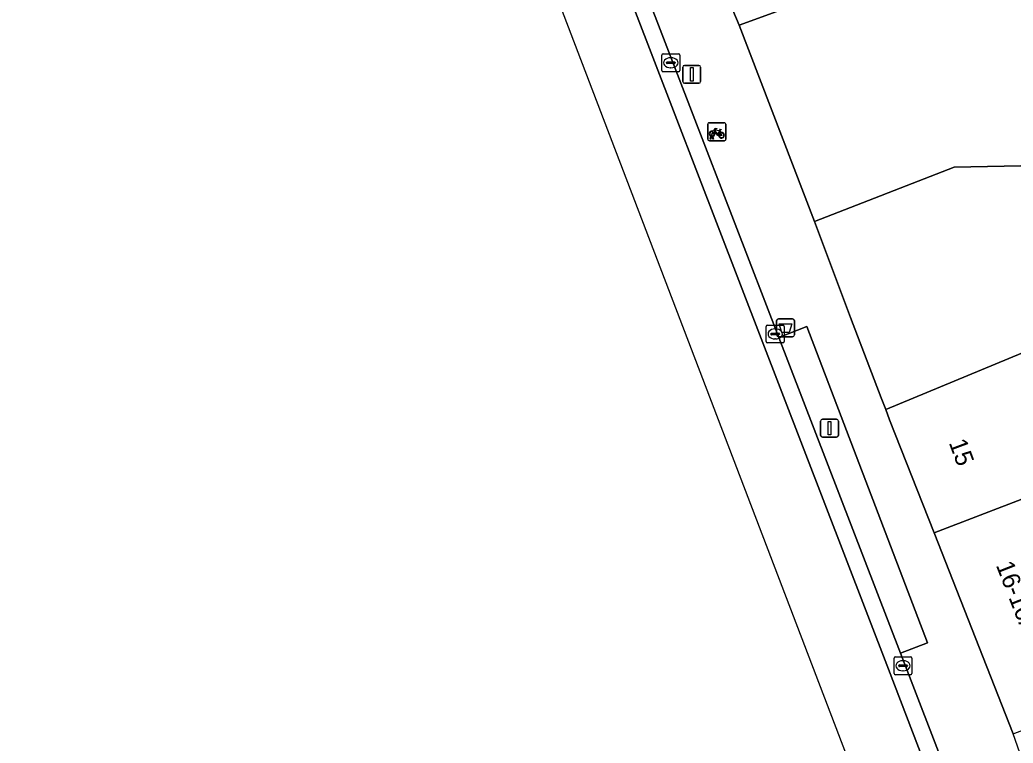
# Model space of a CAD drawing. Extents: x 160856 to 161310, y 384024 to 384878.
# Drawn here: x 160889.1 to 160944.6, y 384634.5 to 384674.8 of the extents above; entities that cross this region are included whole.
import ezdxf

# ---------------------------------------------------------------- set-up
doc = ezdxf.new("R2010")
doc.units = 0
for name, color, linetype in [('IMGEO_Afvalbak', 7, 'Continuous'), ('IMGEO_Fietsenrek', 7, 'Continuous'), ('IMGEO_Fietspad_gesloten', 7, 'Continuous'), ('IMGEO_Fietspad_open', 7, 'Continuous'), ('IMGEO_Kolk', 7, 'Continuous'), ('IMGEO_Lichtmast', 7, 'Continuous'), ('IMGEO_Pand', 7, 'Continuous'), ('IMGEO_Pand_nummerreeks', 7, 'Continuous'), ('IMGEO_Verkeerseiland_open', 7, 'Continuous'), ('IMGEO_Voetpad_open', 7, 'Continuous')]:
    doc.layers.add(name, color=color, linetype=linetype)

msp = doc.modelspace()

# ---------------------------------------------------------------- linework, layer by layer
at = {"layer": 'IMGEO_Afvalbak'}
for p, q in [((160931.361, 384657.241), (160931.361, 384658.041)), ((160931.361, 384658.041), (160931.361, 384657.241)), ((160931.461, 384658.141), (160932.251, 384658.141)), ((160932.251, 384658.141), (160931.461, 384658.141)), ((160932.351, 384658.041), (160932.351, 384657.241)), ((160932.351, 384657.241), (160932.351, 384658.041)), ((160932.251, 384657.141), (160931.461, 384657.141)), ((160931.461, 384657.141), (160932.251, 384657.141))]:
    msp.add_line(p, q, dxfattribs=at)
msp.add_lwpolyline([(160931.504, 384657.855), (160932.208, 384657.855), (160932.059, 384657.385), (160931.653, 384657.385), (160931.504, 384657.855)], dxfattribs=at)
for centre, start, end in [((160931.461, 384658.041), 90, 180), ((160931.461, 384658.041), 90, 180), ((160932.251, 384658.041), 0, 90), ((160932.251, 384658.041), 360, 90), ((160931.461, 384657.241), 180, 270), ((160931.461, 384657.241), 180, 270), ((160932.251, 384657.241), 270, 0), ((160932.251, 384657.241), 270, 0)]:
    msp.add_arc(centre, 0.1, start, end, dxfattribs=at)
at = {"layer": 'IMGEO_Fietsenrek'}
for p, q in [((160927.524, 384668.162), (160927.524, 384669.003)), ((160927.524, 384669.003), (160927.524, 384668.162)), ((160927.599, 384669.087), (160928.44, 384669.087)), ((160928.44, 384669.087), (160927.599, 384669.087)), ((160928.524, 384669.012), (160928.524, 384668.171)), ((160928.524, 384668.171), (160928.524, 384669.012)), ((160928.211, 384668.636), (160928.247, 384668.541)), ((160928.449, 384668.087), (160927.608, 384668.087)), ((160927.608, 384668.087), (160928.449, 384668.087)), ((160927.651, 384668.171), (160927.69, 384668.331)), ((160927.685, 384668.171), (160927.651, 384668.171)), ((160927.72, 384668.319), (160927.685, 384668.171)), ((160927.762, 384668.343), (160927.761, 384668.347)), ((160927.803, 384668.171), (160927.769, 384668.313)), ((160927.793, 384668.354), (160927.794, 384668.347)), ((160927.801, 384668.317), (160927.836, 384668.171)), ((160927.836, 384668.171), (160927.803, 384668.171))]:
    msp.add_line(p, q, dxfattribs=at)
for points in [[(160927.858, 384668.561), (160927.806, 384668.471), (160927.766, 384668.446), (160927.767, 384668.493), (160927.822, 384668.587)], [(160927.837, 384668.613), (160927.932, 384668.777), (160928.018, 384668.763), (160928.02, 384668.754), (160927.964, 384668.743), (160927.937, 384668.698), (160928.193, 384668.657)], [(160928.133, 384668.369), (160928.083, 384668.369), (160927.892, 384668.62), (160927.873, 384668.588)], [(160928.18, 384668.632), (160927.923, 384668.673), (160927.906, 384668.644), (160928.073, 384668.424), (160928.18, 384668.632)], [(160928.228, 384668.534), (160928.198, 384668.611), (160928.089, 384668.393), (160928.132, 384668.393)], [(160928.162, 384668.393), (160928.282, 384668.392), (160928.238, 384668.506)], [(160928.258, 384668.513), (160928.313, 384668.368), (160928.163, 384668.368)], [(160928.193, 384668.657), (160928.218, 384668.706), (160928.212, 384668.71), (160928.189, 384668.714), (160928.177, 384668.721), (160928.176, 384668.724), (160928.178, 384668.729), (160928.273, 384668.714), (160928.275, 384668.704), (160928.265, 384668.691), (160928.253, 384668.685), (160928.239, 384668.691), (160928.211, 384668.636)]]:
    msp.add_lwpolyline(points, dxfattribs=at)
for centre, radius, start, end in [((160927.602, 384669.009), 0.0779, 92.4484, 184.2845), ((160927.602, 384669.009), 0.0779, 92.4484, 184.2845), ((160928.446, 384669.009), 0.0779, 2.4484, 94.2845), ((160928.446, 384669.009), 0.0779, 2.4484, 94.2845), ((160927.764, 384668.472), 0.159, 62.6766, 242.1369), ((160927.764, 384668.472), 0.129, 63.3192, 238.903), ((160927.764, 384668.472), 0.129, 283.6043, 43.4302), ((160927.764, 384668.472), 0.159, 283.5766, 46.6042), ((160928.291, 384668.388), 0.159, 113.3408, 178.3217), ((160928.291, 384668.388), 0.159, 187.0065, 105.7708), ((160928.291, 384668.388), 0.129, 113.923, 177.9556), ((160928.291, 384668.388), 0.129, 188.6715, 104.5883), ((160927.602, 384668.165), 0.0779, 182.4484, 274.2845), ((160927.602, 384668.165), 0.0779, 182.4484, 274.2845), ((160927.744, 384668.343), 0.0499, 12.8025, 158.6934), ((160927.764, 384668.472), 0.159, 253.9967, 271.7867), ((160927.744, 384668.343), 0.0174, 12.8025, 163.4502), ((160927.764, 384668.472), 0.129, 253.415, 269.0204), ((160928.446, 384668.165), 0.0779, 272.4484, 4.2845), ((160928.446, 384668.165), 0.0779, 272.4484, 4.2845)]:
    msp.add_arc(centre, radius, start, end, dxfattribs=at)
at = {"layer": 'IMGEO_Fietspad_gesloten'}
msp.add_lwpolyline([(160952.428, 384599.868), (160937.604, 384638.593), (160892.484, 384755.839), (160890.883, 384755.238), (160892.527, 384749.494), (160889.824, 384754.841), (160889.132, 384754.582), (160951.015, 384592.51), (160969.346, 384573.161), (160977.866, 384562.895)], dxfattribs=at)
at = {"layer": 'IMGEO_Fietspad_open'}
for points in [[(160921.747, 384682.423), (160893.385, 384756.183), (160892.484, 384755.839), (160937.604, 384638.593), (160952.428, 384599.868)], [(160953.42, 384600.161), (160938.279, 384639.478), (160931.483, 384657.104), (160921.747, 384682.423)]]:
    msp.add_lwpolyline(points, dxfattribs=at)
at = {"layer": 'IMGEO_Kolk'}
for p, q in [((160924.957, 384672.01), (160924.957, 384672.862)), ((160925.032, 384672.936), (160925.884, 384672.936)), ((160925.958, 384672.862), (160925.958, 384672.01)), ((160925.216, 384672.43), (160925.216, 384672.442)), ((160925.654, 384672.393), (160925.256, 384672.393)), ((160925.259, 384672.479), (160925.657, 384672.479)), ((160925.445, 384672.716), (160925.47, 384672.716)), ((160925.7, 384672.442), (160925.7, 384672.43)), ((160925.884, 384671.936), (160925.032, 384671.936)), ((160925.468, 384672.156), (160925.443, 384672.156)), ((160930.782, 384656.87), (160930.782, 384657.722)), ((160930.857, 384657.796), (160931.709, 384657.796)), ((160931.27, 384657.576), (160931.295, 384657.576)), ((160931.783, 384657.722), (160931.783, 384656.87)), ((160931.709, 384656.796), (160930.857, 384656.796)), ((160931.041, 384657.29), (160931.041, 384657.302)), ((160931.479, 384657.253), (160931.081, 384657.253)), ((160931.084, 384657.339), (160931.482, 384657.339)), ((160931.293, 384657.016), (160931.268, 384657.016)), ((160931.525, 384657.302), (160931.525, 384657.29)), ((160937.915, 384638.348), (160937.915, 384639.2)), ((160937.99, 384639.274), (160938.842, 384639.274)), ((160938.403, 384639.054), (160938.428, 384639.054)), ((160938.916, 384639.2), (160938.916, 384638.348)), ((160938.174, 384638.768), (160938.174, 384638.78)), ((160938.612, 384638.731), (160938.214, 384638.731)), ((160938.217, 384638.817), (160938.615, 384638.817)), ((160938.426, 384638.494), (160938.401, 384638.494)), ((160938.658, 384638.78), (160938.658, 384638.768)), ((160938.842, 384638.274), (160937.99, 384638.274))]:
    msp.add_line(p, q, dxfattribs=at)
for points in [[(160924.957, 384672.01), (160924.957, 384672.862)], [(160925.032, 384672.936), (160925.884, 384672.936)], [(160925.958, 384672.862), (160925.958, 384672.01)], [(160925.884, 384671.936), (160925.032, 384671.936)], [(160930.782, 384656.87), (160930.782, 384657.722)], [(160930.857, 384657.796), (160931.709, 384657.796)], [(160931.783, 384657.722), (160931.783, 384656.87)], [(160931.709, 384656.796), (160930.857, 384656.796)], [(160937.915, 384638.348), (160937.915, 384639.2)], [(160937.99, 384639.274), (160938.842, 384639.274)], [(160938.916, 384639.2), (160938.916, 384638.348)], [(160938.842, 384638.274), (160937.99, 384638.274)]]:
    msp.add_lwpolyline(points, dxfattribs=at)
for centre, radius, start, end in [((160925.034, 384672.86), 0.0765, 91.552, 178.448), ((160925.034, 384672.86), 0.0765, 91.552, 178.448), ((160925.882, 384672.86), 0.0765, 1.552, 88.448), ((160925.882, 384672.86), 0.0765, 1.552, 88.448), ((160925.256, 384672.439), 0.0403, 85.8775, 175.7526), ((160925.253, 384672.429), 0.0366, 178.938, 274.7102), ((160925.657, 384672.436), 0.043, 264.8664, 352.4533), ((160925.661, 384672.441), 0.0386, 1.7309, 96.639), ((160925.034, 384672.012), 0.0765, 181.552, 268.448), ((160925.034, 384672.012), 0.0765, 181.552, 268.448), ((160925.882, 384672.012), 0.0765, 271.552, 358.448), ((160925.882, 384672.012), 0.0765, 271.552, 358.448), ((160930.859, 384657.72), 0.0765, 91.552, 178.448), ((160930.859, 384657.72), 0.0765, 91.552, 178.448), ((160931.707, 384657.72), 0.0765, 1.552, 88.448), ((160931.707, 384657.72), 0.0765, 1.552, 88.448), ((160930.859, 384656.872), 0.0765, 181.552, 268.448), ((160930.859, 384656.872), 0.0765, 181.552, 268.448), ((160931.081, 384657.299), 0.0403, 85.8775, 175.7526), ((160931.078, 384657.289), 0.0366, 178.938, 274.7102), ((160931.482, 384657.296), 0.043, 264.8664, 352.4533), ((160931.486, 384657.301), 0.0386, 1.7309, 96.639), ((160931.707, 384656.872), 0.0765, 271.552, 358.448), ((160931.707, 384656.872), 0.0765, 271.552, 358.448), ((160937.992, 384639.198), 0.0765, 91.552, 178.448), ((160937.992, 384639.198), 0.0765, 91.552, 178.448), ((160938.84, 384639.198), 0.0765, 1.552, 88.448), ((160938.84, 384639.198), 0.0765, 1.552, 88.448), ((160938.214, 384638.777), 0.0403, 85.8775, 175.7526), ((160938.211, 384638.767), 0.0366, 178.938, 274.7102), ((160938.615, 384638.774), 0.043, 264.8664, 352.4533), ((160938.619, 384638.779), 0.0386, 1.7309, 96.639), ((160937.992, 384638.35), 0.0765, 181.552, 268.448), ((160937.992, 384638.35), 0.0765, 181.552, 268.448), ((160938.84, 384638.35), 0.0765, 271.552, 358.448), ((160938.84, 384638.35), 0.0765, 271.552, 358.448)]:
    msp.add_arc(centre, radius, start, end, dxfattribs=at)
for centre, major_axis, ratio, start_param, end_param in [((160925.444, 384672.436), (-0.387, 0.002), 0.722429, 4.712389, 7.853982), ((160925.469, 384672.436), (-0.39, 0.002), 0.717154, 1.570796, 4.712389), ((160931.269, 384657.296), (-0.387, 0.002), 0.722429, 4.712389, 7.853982), ((160931.294, 384657.296), (-0.39, 0.002), 0.717154, 1.570796, 4.712389), ((160938.402, 384638.774), (-0.387, 0.002), 0.722429, 4.712389, 7.853982), ((160938.427, 384638.774), (-0.39, 0.002), 0.717154, 1.570796, 4.712389)]:
    msp.add_ellipse(centre, major_axis=major_axis, ratio=ratio, start_param=start_param, end_param=end_param, dxfattribs=at)
at = {"layer": 'IMGEO_Lichtmast'}
for p, q in [((160926.127, 384671.389), (160926.127, 384672.189)), ((160926.127, 384672.189), (160926.127, 384671.389)), ((160926.227, 384672.289), (160927.017, 384672.289)), ((160927.017, 384672.289), (160926.227, 384672.289)), ((160927.117, 384672.189), (160927.117, 384671.389)), ((160927.117, 384671.389), (160927.117, 384672.189)), ((160927.017, 384671.289), (160926.227, 384671.289)), ((160926.227, 384671.289), (160927.017, 384671.289)), ((160933.817, 384651.635), (160933.817, 384652.435)), ((160933.817, 384652.435), (160933.817, 384651.635)), ((160933.917, 384652.535), (160934.707, 384652.535)), ((160934.707, 384652.535), (160933.917, 384652.535)), ((160934.807, 384652.435), (160934.807, 384651.635)), ((160934.807, 384651.635), (160934.807, 384652.435)), ((160934.707, 384651.535), (160933.917, 384651.535)), ((160933.917, 384651.535), (160934.707, 384651.535))]:
    msp.add_line(p, q, dxfattribs=at)
for points in [[(160926.547, 384672.164), (160926.697, 384672.164), (160926.697, 384671.414), (160926.547, 384671.414), (160926.547, 384672.164)], [(160934.237, 384652.41), (160934.387, 384652.41), (160934.387, 384651.66), (160934.237, 384651.66), (160934.237, 384652.41)]]:
    msp.add_lwpolyline(points, dxfattribs=at)
for centre, start, end in [((160926.227, 384672.189), 90, 180), ((160926.227, 384672.189), 90, 180), ((160927.017, 384672.189), 0, 90), ((160927.017, 384672.189), 360, 90), ((160926.227, 384671.389), 180, 270), ((160926.227, 384671.389), 180, 270), ((160927.017, 384671.389), 270, 0), ((160927.017, 384671.389), 270, 0), ((160933.917, 384652.435), 90, 180), ((160933.917, 384652.435), 90, 180), ((160934.707, 384652.435), 0, 90), ((160934.707, 384652.435), 360, 90), ((160933.917, 384651.635), 180, 270), ((160933.917, 384651.635), 180, 270), ((160934.707, 384651.635), 270, 0), ((160934.707, 384651.635), 270, 0)]:
    msp.add_arc(centre, 0.1, start, end, dxfattribs=at)
at = {"layer": 'IMGEO_Pand'}
for points in [[(160955.594, 384666.434), (160955.52, 384666.637), (160964.692, 384669.97), (160960.908, 384674.794), (160957.27, 384684.595), (160955.307, 384684.002), (160954.733, 384683.794), (160929.276, 384674.544), (160933.47, 384663.572), (160941.279, 384666.602), (160945.923, 384666.697), (160951.642, 384666.521)], [(160937.451, 384653.082), (160945.078, 384656.249), (160957.517, 384658.886), (160971.859, 384657.86), (160971.358, 384659.52), (160970.725, 384659.329), (160967.658, 384669.485), (160956.022, 384665.257), (160955.594, 384666.434), (160951.642, 384666.521), (160945.923, 384666.697), (160941.279, 384666.602), (160933.47, 384663.572), (160935.209, 384658.967), (160935.494, 384658.22), (160937.202, 384653.736)], [(160937.451, 384653.082), (160937.67, 384652.508), (160940.157, 384646.186), (160947.852, 384649.157), (160948.047, 384648.651), (160963.147, 384654.482), (160973.559, 384653.621), (160972.563, 384656.918), (160972.179, 384656.802), (160971.859, 384657.86), (160957.517, 384658.886), (160945.078, 384656.249)], [(161023.199, 384638.753), (161023.706, 384645.1), (161011.266, 384646.094), (161011.607, 384650.352), (161000, 384651.318), (160973.59, 384653.518), (160973.559, 384653.621), (160963.147, 384654.482), (160948.047, 384648.651), (160947.852, 384649.157), (160940.157, 384646.186), (160944.571, 384634.966), (160949.236, 384636.767), (160959.912, 384640.889), (160960.282, 384639.932), (160968.473, 384643.094), (160988.813, 384641.433), (161009.711, 384639.726)]]:
    msp.add_lwpolyline(points, close=True, dxfattribs=at)
at = {"layer": 'IMGEO_Verkeerseiland_open'}
msp.add_lwpolyline([(160931.483, 384657.104), (160938.279, 384639.478), (160939.775, 384640.046), (160933.049, 384657.72)], close=True, dxfattribs=at)
at = {"layer": 'IMGEO_Voetpad_open'}
for points in [[(160929.794, 384678.201), (160928.902, 384677.875), (160928.003, 384677.547), (160928.927, 384675.368), (160929.276, 384674.544), (160954.733, 384683.794), (160955.307, 384684.002), (160957.27, 384684.595), (160962.626, 384686.212), (160966.621, 384687.573), (160968.254, 384688.176), (160968.1, 384688.831), (160974.983, 384690.451), (160981.722, 384692.037)], [(160929.276, 384674.544), (160928.927, 384675.368), (160928.003, 384677.547), (160926.724, 384680.788), (160925.586, 384683.954), (160921.747, 384682.423), (160931.483, 384657.104), (160933.049, 384657.72), (160939.775, 384640.046), (160938.279, 384639.478), (160953.42, 384600.161)], [(160977.218, 384580.587), (160973.995, 384584.418), (160970.483, 384581.386), (160960.23, 384594.229), (160957.323, 384601.772), (160951.527, 384616.811), (160951.057, 384618.029), (160949.182, 384622.895), (160948.94, 384623.522), (160944.938, 384633.907), (160944.571, 384634.966), (160940.157, 384646.186), (160937.67, 384652.508), (160937.451, 384653.082), (160937.202, 384653.736), (160935.494, 384658.22), (160935.209, 384658.967), (160933.47, 384663.572), (160929.276, 384674.544)]]:
    msp.add_lwpolyline(points, dxfattribs=at)

# ---------------------------------------------------------------- texts
at = {"layer": 'IMGEO_Pand_nummerreeks'}
for s, rotation, p in [('15', 290.5228, (160940.96, 384651.228)), ('16-16A', 291.4014, (160943.588, 384644.389))]:
    msp.add_text(s, height=1, rotation=rotation, dxfattribs=at).set_placement(p)

doc.saveas('drawing.dxf')
